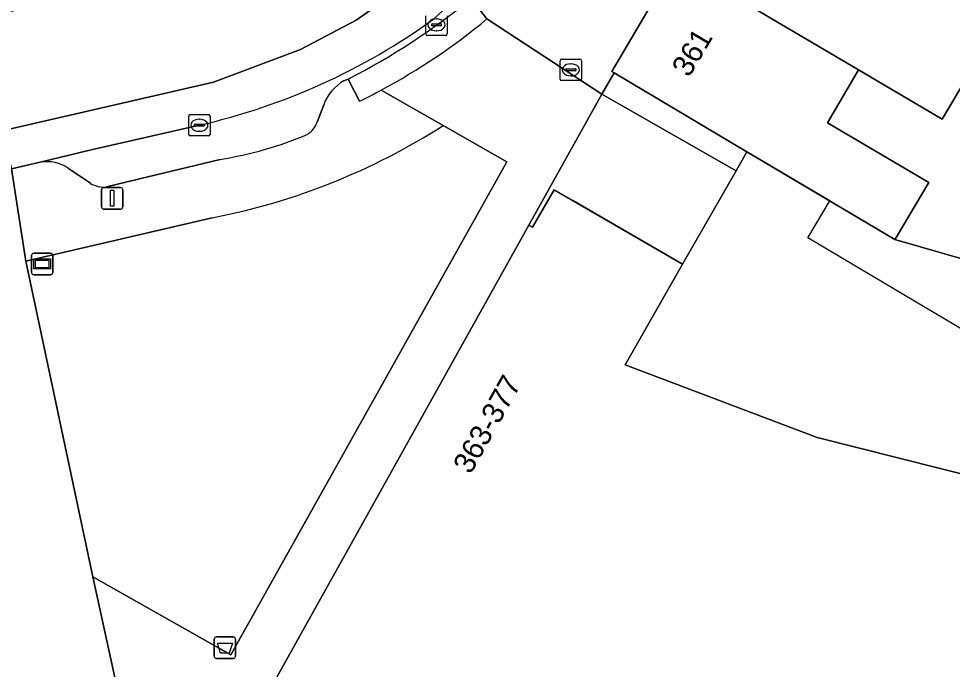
# Model space of a CAD drawing. Extents: x 160554 to 161248, y 385329 to 386506.
# Drawn here: x 160787.27 to 160830.85, y 385700.75 to 385731.11 of the extents above; entities that cross this region are included whole.
import ezdxf

# ---------------------------------------------------------------- set-up
doc = ezdxf.new("R2010")
doc.units = 0
for name, color, linetype in [('IMGEO_Afvalbak', 7, 'Continuous'), ('IMGEO_Brandkraan', 7, 'Continuous'), ('IMGEO_Erf', 7, 'Continuous'), ('IMGEO_Groenvoorziening', 7, 'Continuous'), ('IMGEO_Informatiebord', 7, 'Continuous'), ('IMGEO_Kolk', 7, 'Continuous'), ('IMGEO_Lichtmast', 7, 'Continuous'), ('IMGEO_Muur', 7, 'Continuous'), ('IMGEO_Pand', 7, 'Continuous'), ('IMGEO_Pand_nummerreeks', 7, 'Continuous'), ('IMGEO_Pand_overbouw', 7, 'Continuous'), ('IMGEO_Parkeervlak_open', 7, 'Continuous'), ('IMGEO_Rijbaan_lokaal_gesloten', 7, 'Continuous'), ('IMGEO_Rijbaan_lokaal_open', 7, 'Continuous'), ('IMGEO_Voetpad_open', 7, 'Continuous')]:
    doc.layers.add(name, color=color, linetype=linetype)

msp = doc.modelspace()

# ---------------------------------------------------------------- linework, layer by layer
at = {"layer": 'IMGEO_Afvalbak'}
for p, q in [((160796.402, 385701.36), (160796.402, 385702.16)), ((160796.402, 385702.16), (160796.402, 385701.36)), ((160796.502, 385702.26), (160797.292, 385702.26)), ((160797.292, 385702.26), (160796.502, 385702.26)), ((160797.392, 385702.16), (160797.392, 385701.36)), ((160797.392, 385701.36), (160797.392, 385702.16)), ((160797.292, 385701.26), (160796.502, 385701.26)), ((160796.502, 385701.26), (160797.292, 385701.26))]:
    msp.add_line(p, q, dxfattribs=at)
msp.add_lwpolyline([(160796.545, 385701.974), (160797.249, 385701.974), (160797.1, 385701.504), (160796.694, 385701.504), (160796.545, 385701.974)], dxfattribs=at)
for centre, start, end in [((160796.502, 385702.16), 90, 180), ((160796.502, 385702.16), 90, 180), ((160797.292, 385702.16), 0, 90), ((160797.292, 385702.16), 360, 90), ((160796.502, 385701.36), 180, 270), ((160796.502, 385701.36), 180, 270), ((160797.292, 385701.36), 270, 0), ((160797.292, 385701.36), 270, 0)]:
    msp.add_arc(centre, 0.1, start, end, dxfattribs=at)
at = {"layer": 'IMGEO_Brandkraan'}
for p, q in [((160812.546, 385728.296), (160812.546, 385729.148)), ((160812.621, 385729.222), (160813.473, 385729.222)), ((160813.034, 385729.002), (160813.059, 385729.002)), ((160813.547, 385729.148), (160813.547, 385728.296)), ((160812.805, 385728.716), (160812.805, 385728.728)), ((160813.243, 385728.679), (160812.845, 385728.679)), ((160812.848, 385728.765), (160813.246, 385728.765)), ((160813.289, 385728.728), (160813.289, 385728.716)), ((160813.473, 385728.222), (160812.621, 385728.222)), ((160813.057, 385728.442), (160813.032, 385728.442))]:
    msp.add_line(p, q, dxfattribs=at)
for points in [[(160812.546, 385728.296), (160812.546, 385729.148)], [(160812.621, 385729.222), (160813.473, 385729.222)], [(160813.547, 385729.148), (160813.547, 385728.296)], [(160813.473, 385728.222), (160812.621, 385728.222)]]:
    msp.add_lwpolyline(points, dxfattribs=at)
for centre, radius, start, end in [((160812.623, 385729.146), 0.0765, 91.552, 178.448), ((160812.623, 385729.146), 0.0765, 91.552, 178.448), ((160813.471, 385729.146), 0.0765, 1.552, 88.448), ((160813.471, 385729.146), 0.0765, 1.552, 88.448), ((160812.845, 385728.725), 0.0403, 85.8775, 175.7526), ((160812.842, 385728.715), 0.0366, 178.938, 274.7102), ((160813.246, 385728.722), 0.043, 264.8664, 352.4533), ((160813.25, 385728.727), 0.0386, 1.7309, 96.639), ((160812.623, 385728.298), 0.0765, 181.552, 268.448), ((160812.623, 385728.298), 0.0765, 181.552, 268.448), ((160813.471, 385728.298), 0.0765, 271.552, 358.448), ((160813.471, 385728.298), 0.0765, 271.552, 358.448)]:
    msp.add_arc(centre, radius, start, end, dxfattribs=at)
for centre, major_axis, ratio, start_param, end_param in [((160813.033, 385728.722), (-0.387, 0.002), 0.722429, 4.712389, 7.853982), ((160813.058, 385728.722), (-0.39, 0.002), 0.717154, 1.570796, 4.712389)]:
    msp.add_ellipse(centre, major_axis=major_axis, ratio=ratio, start_param=start_param, end_param=end_param, dxfattribs=at)
at = {"layer": 'IMGEO_Erf'}
msp.add_lwpolyline([(160833.175, 385731.152), (160831.67, 385728.598), (160830.385, 385726.417), (160826.479, 385728.719), (160826.198, 385728.242), (160825.026, 385726.254), (160829.75, 385723.471), (160828.234, 385720.899), (160828.176, 385720.801), (160856.562, 385712.649), (160882.401, 385760.458)], dxfattribs=at)
at = {"layer": 'IMGEO_Groenvoorziening'}
msp.add_lwpolyline([(160796.304, 385721.821), (160787.609, 385719.8), (160790.739, 385705.06), (160797.182, 385701.424), (160810.062, 385724.425), (160807.083, 385726.127)], dxfattribs=at)
msp.add_arc((160790.483, 385752.036), 30.771, 280.9042, 302.6472, dxfattribs=at)
at = {"layer": 'IMGEO_Informatiebord'}
for p, q in [((160787.972, 385720.166), (160788.762, 385720.166)), ((160788.762, 385720.166), (160787.972, 385720.166)), ((160787.872, 385719.266), (160787.872, 385720.066)), ((160787.872, 385720.066), (160787.872, 385719.266)), ((160788.862, 385720.066), (160788.862, 385719.266)), ((160788.862, 385719.266), (160788.862, 385720.066)), ((160788.762, 385719.166), (160787.972, 385719.166)), ((160787.972, 385719.166), (160788.762, 385719.166))]:
    msp.add_line(p, q, dxfattribs=at)
for points in [[(160787.973, 385719.898), (160788.761, 385719.898), (160788.761, 385719.434), (160787.973, 385719.434), (160787.973, 385719.898)], [(160788.038, 385719.833), (160788.038, 385719.499), (160788.696, 385719.499), (160788.696, 385719.833), (160788.038, 385719.833)]]:
    msp.add_lwpolyline(points, dxfattribs=at)
for centre, start, end in [((160787.972, 385720.066), 90, 180), ((160787.972, 385720.066), 90, 180), ((160788.762, 385720.066), 0, 90), ((160788.762, 385720.066), 360, 90), ((160787.972, 385719.266), 180, 270), ((160787.972, 385719.266), 180, 270), ((160788.762, 385719.266), 270, 0), ((160788.762, 385719.266), 270, 0)]:
    msp.add_arc(centre, 0.1, start, end, dxfattribs=at)
at = {"layer": 'IMGEO_Kolk'}
for p, q in [((160806.276, 385730.396), (160806.276, 385731.248)), ((160806.764, 385731.102), (160806.789, 385731.102)), ((160807.277, 385731.248), (160807.277, 385730.396)), ((160806.535, 385730.816), (160806.535, 385730.828)), ((160806.973, 385730.779), (160806.575, 385730.779)), ((160806.578, 385730.865), (160806.976, 385730.865)), ((160807.019, 385730.828), (160807.019, 385730.816)), ((160807.203, 385730.322), (160806.351, 385730.322)), ((160806.787, 385730.542), (160806.762, 385730.542)), ((160795.207, 385725.712), (160795.207, 385726.564)), ((160795.282, 385726.638), (160796.134, 385726.638)), ((160795.695, 385726.418), (160795.72, 385726.418)), ((160796.208, 385726.564), (160796.208, 385725.712)), ((160795.466, 385726.132), (160795.466, 385726.144)), ((160795.904, 385726.095), (160795.506, 385726.095)), ((160795.509, 385726.181), (160795.907, 385726.181)), ((160795.718, 385725.858), (160795.693, 385725.858)), ((160795.95, 385726.144), (160795.95, 385726.132)), ((160796.134, 385725.638), (160795.282, 385725.638))]:
    msp.add_line(p, q, dxfattribs=at)
for points in [[(160806.276, 385730.396), (160806.276, 385731.248)], [(160807.277, 385731.248), (160807.277, 385730.396)], [(160807.203, 385730.322), (160806.351, 385730.322)], [(160795.207, 385725.712), (160795.207, 385726.564)], [(160795.282, 385726.638), (160796.134, 385726.638)], [(160796.208, 385726.564), (160796.208, 385725.712)], [(160796.134, 385725.638), (160795.282, 385725.638)]]:
    msp.add_lwpolyline(points, dxfattribs=at)
for centre, radius, start, end in [((160806.575, 385730.825), 0.0403, 85.8775, 175.7526), ((160806.572, 385730.815), 0.0366, 178.938, 274.7102), ((160806.976, 385730.822), 0.043, 264.8664, 352.4533), ((160806.98, 385730.827), 0.0386, 1.7309, 96.639), ((160806.353, 385730.398), 0.0765, 181.552, 268.448), ((160806.353, 385730.398), 0.0765, 181.552, 268.448), ((160807.201, 385730.398), 0.0765, 271.552, 358.448), ((160807.201, 385730.398), 0.0765, 271.552, 358.448), ((160795.284, 385726.562), 0.0765, 91.552, 178.448), ((160795.284, 385726.562), 0.0765, 91.552, 178.448), ((160796.132, 385726.562), 0.0765, 1.552, 88.448), ((160796.132, 385726.562), 0.0765, 1.552, 88.448), ((160795.506, 385726.141), 0.0403, 85.8775, 175.7526), ((160795.503, 385726.131), 0.0366, 178.938, 274.7102), ((160795.907, 385726.138), 0.043, 264.8664, 352.4533), ((160795.911, 385726.143), 0.0386, 1.7309, 96.639), ((160795.284, 385725.714), 0.0765, 181.552, 268.448), ((160795.284, 385725.714), 0.0765, 181.552, 268.448), ((160796.132, 385725.714), 0.0765, 271.552, 358.448), ((160796.132, 385725.714), 0.0765, 271.552, 358.448)]:
    msp.add_arc(centre, radius, start, end, dxfattribs=at)
for centre, major_axis, ratio, start_param, end_param in [((160806.763, 385730.822), (-0.387, 0.002), 0.722429, 4.712389, 7.853982), ((160806.788, 385730.822), (-0.39, 0.002), 0.717154, 1.570796, 4.712389), ((160795.694, 385726.138), (-0.387, 0.002), 0.722429, 4.712389, 7.853982), ((160795.719, 385726.138), (-0.39, 0.002), 0.717154, 1.570796, 4.712389)]:
    msp.add_ellipse(centre, major_axis=major_axis, ratio=ratio, start_param=start_param, end_param=end_param, dxfattribs=at)
at = {"layer": 'IMGEO_Lichtmast'}
for p, q in [((160791.238, 385723.23), (160792.028, 385723.23)), ((160792.028, 385723.23), (160791.238, 385723.23)), ((160791.138, 385722.33), (160791.138, 385723.13)), ((160791.138, 385723.13), (160791.138, 385722.33)), ((160792.128, 385723.13), (160792.128, 385722.33)), ((160792.128, 385722.33), (160792.128, 385723.13)), ((160792.028, 385722.23), (160791.238, 385722.23)), ((160791.238, 385722.23), (160792.028, 385722.23))]:
    msp.add_line(p, q, dxfattribs=at)
msp.add_lwpolyline([(160791.558, 385723.105), (160791.708, 385723.105), (160791.708, 385722.355), (160791.558, 385722.355), (160791.558, 385723.105)], dxfattribs=at)
for centre, start, end in [((160791.238, 385723.13), 90, 180), ((160791.238, 385723.13), 90, 180), ((160792.028, 385723.13), 0, 90), ((160792.028, 385723.13), 360, 90), ((160791.238, 385722.33), 180, 270), ((160791.238, 385722.33), 180, 270), ((160792.028, 385722.33), 270, 0), ((160792.028, 385722.33), 270, 0)]:
    msp.add_arc(centre, 0.1, start, end, dxfattribs=at)
at = {"layer": 'IMGEO_Muur'}
msp.add_lwpolyline([(160856.562, 385712.649), (160828.176, 385720.801)], dxfattribs=at)
at = {"layer": 'IMGEO_Pand'}
for points in [[(160830.7, 385732.61), (160828.823, 385733.716), (160820.761, 385738.466), (160817.958, 385733.74), (160826.479, 385728.719), (160830.385, 385726.417), (160831.67, 385728.598), (160833.175, 385731.152)], [(160826.198, 385728.242), (160826.479, 385728.719), (160817.958, 385733.74), (160814.959, 385728.649), (160815.065, 385728.586), (160821.266, 385724.904), (160828.176, 385720.801), (160828.234, 385720.899), (160829.75, 385723.471), (160825.026, 385726.254)], [(160815.065, 385728.586), (160814.495, 385727.589), (160815.364, 385727.093), (160820.756, 385724.011), (160821.266, 385724.904)], [(160851.659, 385703.57), (160847.383, 385705.807), (160824.547, 385711.575), (160815.584, 385714.965), (160818.265, 385719.655), (160813.137, 385722.623), (160812.272, 385723.124), (160811.259, 385721.375), (160811.085, 385721.473), (160799.242, 385700.242), (160807.995, 385695.338), (160812.372, 385675.602), (160812.932, 385673.076), (160831.957, 385677.464), (160836.882, 385676.206), (160840.418, 385682.754)]]:
    msp.add_lwpolyline(points, close=True, dxfattribs=at)
at = {"layer": 'IMGEO_Pand_overbouw'}
msp.add_lwpolyline([(160845.865, 385707.972), (160824.111, 385720.889), (160825.132, 385722.609), (160821.266, 385724.904), (160815.065, 385728.586), (160814.495, 385727.589), (160811.085, 385721.473), (160799.242, 385700.242), (160807.995, 385695.338), (160812.372, 385675.602), (160812.932, 385673.076), (160807.713, 385671.926), (160800.168, 385670.228), (160806.16, 385643.282)], dxfattribs=at)
msp.add_lwpolyline([(160814.495, 385727.589), (160811.085, 385721.473), (160811.259, 385721.375), (160812.272, 385723.124), (160818.265, 385719.655), (160820.756, 385724.011), (160815.364, 385727.093)], close=True, dxfattribs=at)
at = {"layer": 'IMGEO_Parkeervlak_open'}
for points in [[(160820.622, 385746.796), (160822.533, 385750), (160829.162, 385761.115), (160827.585, 385762.049), (160825.271, 385758.149), (160820.43, 385750), (160815.067, 385740.874), (160814.4, 385739.76), (160813.682, 385738.667), (160812.914, 385737.599), (160812.097, 385736.559), (160811.233, 385735.551), (160810.325, 385734.578), (160809.373, 385733.642), (160806.634, 385731.089)], [(160802.457, 385728.213), (160802.648, 385728.294)], [(160801.2, 385726.278), (160801.511, 385727.097)], [(160795.707, 385726.14), (160790.656, 385724.991), (160788.279, 385724.419)], [(160791.372, 385723.26), (160793.295, 385723.736), (160796.671, 385724.545)], [(160789.601, 385724.118), (160790.624, 385723.428)]]:
    msp.add_lwpolyline(points, dxfattribs=at)
for centre, radius, start, end in [((160787.733, 385757.398), 32.703, 297.134, 309.1811), ((160789.017, 385755.448), 30.061, 282.8578, 305.8752), ((160803.534, 385726.341), 2.16, 119.9138, 159.5123), ((160800.121, 385726.678), 1.151, 304.042, 339.6801), ((160793.962, 385741.648), 17.317, 278.9993, 293.1316), ((160788.558, 385722.592), 1.848, 55.657, 98.6896), ((160791.232, 385724.386), 1.135, 237.5973, 277.0857)]:
    msp.add_arc(centre, radius, start, end, dxfattribs=at)
at = {"layer": 'IMGEO_Rijbaan_lokaal_gesloten'}
msp.add_lwpolyline([(160786.538, 385725.881), (160786.566, 385725.887), (160796.373, 385728.143), (160800.425, 385729.673), (160803.02, 385731.041), (160806.707, 385733.629), (160808.89, 385735.618), (160810.876, 385737.835), (160812.627, 385740.241), (160814.174, 385742.894), (160826.079, 385762.941), (160821.517, 385765.643), (160810.143, 385746.407), (160807.834, 385742.548), (160805.812, 385739.758), (160802.996, 385737.152), (160800.052, 385735.188), (160797.144, 385733.839), (160793.868, 385732.951), (160792.717, 385732.681), (160785.425, 385731.134), (160785.368, 385731.122)], close=True, dxfattribs=at)
for points in [[(160806.707, 385733.629), (160803.02, 385731.041), (160800.425, 385729.673), (160796.373, 385728.143), (160786.566, 385725.887), (160786.538, 385725.881), (160786.933, 385724.11), (160788.279, 385724.419), (160790.656, 385724.991), (160795.707, 385726.14)], [(160806.634, 385731.089), (160809.373, 385733.642)]]:
    msp.add_lwpolyline(points, dxfattribs=at)
msp.add_arc((160789.017, 385755.448), 30.061, 282.8578, 305.8752, dxfattribs=at)
at = {"layer": 'IMGEO_Rijbaan_lokaal_open'}
for points in [[(160820.756, 385724.011), (160815.364, 385727.093), (160814.495, 385727.589), (160811.085, 385721.473), (160811.259, 385721.375), (160812.272, 385723.124), (160813.137, 385722.623), (160818.265, 385719.655)], [(160828.176, 385720.801), (160821.266, 385724.904), (160820.756, 385724.011), (160818.265, 385719.655), (160815.584, 385714.965), (160824.547, 385711.575), (160847.383, 385705.807), (160851.659, 385703.57), (160851.886, 385703.991), (160854.587, 385708.993), (160856.562, 385712.649)]]:
    msp.add_lwpolyline(points, close=True, dxfattribs=at)
at = {"layer": 'IMGEO_Voetpad_open'}
for points in [[(160809.132, 385732.691), (160808.394, 385732.048), (160809.129, 385731.098), (160814.495, 385727.589), (160815.065, 385728.586), (160814.959, 385728.649), (160817.958, 385733.74), (160820.761, 385738.466), (160823.564, 385743.192), (160826.05, 385747.384)], [(160809.129, 385731.098), (160808.394, 385732.048)], [(160811.085, 385721.473), (160814.495, 385727.589), (160809.129, 385731.098)], [(160803.188, 385727.261), (160802.648, 385728.294), (160802.457, 385728.213)], [(160802.648, 385728.294), (160803.188, 385727.261)], [(160804.196, 385727.777), (160807.083, 385726.127), (160810.062, 385724.425), (160797.182, 385701.424), (160790.739, 385705.06), (160792.124, 385698.729), (160797.09, 385695.935), (160799.242, 385700.242), (160811.085, 385721.473)], [(160807.083, 385726.127), (160804.196, 385727.777)], [(160801.511, 385727.097), (160801.2, 385726.278)], [(160796.671, 385724.545), (160793.295, 385723.736), (160791.372, 385723.26)], [(160800.168, 385670.228), (160798.538, 385677.004), (160796.946, 385676.647), (160792.124, 385698.729), (160790.739, 385705.06), (160787.609, 385719.8), (160786.933, 385724.11), (160786.134, 385723.927)], [(160788.279, 385724.419), (160786.933, 385724.11), (160787.609, 385719.8), (160796.304, 385721.821)], [(160790.624, 385723.428), (160789.601, 385724.118)]]:
    msp.add_lwpolyline(points, dxfattribs=at)
for centre, radius, start, end in [((160787.733, 385757.398), 32.703, 297.134, 309.1811), ((160790.152, 385753.963), 29.714, 298.2064, 309.6922), ((160790.152, 385753.963), 29.714, 298.2064, 309.6922), ((160803.534, 385726.341), 2.16, 119.9138, 159.5123), ((160791.139, 385752.042), 27.555, 295.9307, 298.2855), ((160791.139, 385752.042), 27.555, 295.9307, 298.2855), ((160800.121, 385726.678), 1.151, 304.042, 339.6801), ((160790.483, 385752.036), 30.771, 280.9042, 302.6472), ((160793.962, 385741.648), 17.317, 278.9993, 293.1316), ((160788.558, 385722.592), 1.848, 55.657, 98.6896), ((160791.232, 385724.386), 1.135, 237.5973, 277.0857)]:
    msp.add_arc(centre, radius, start, end, dxfattribs=at)

# ---------------------------------------------------------------- texts
at = {"layer": 'IMGEO_Pand_nummerreeks'}
for s, rotation, p in [('361', 59.3355, (160818.563, 385728.331)), ('363-377', 60.7736, (160808.368, 385709.811))]:
    msp.add_text(s, height=1, rotation=rotation, dxfattribs=at).set_placement(p)

doc.saveas('drawing.dxf')
